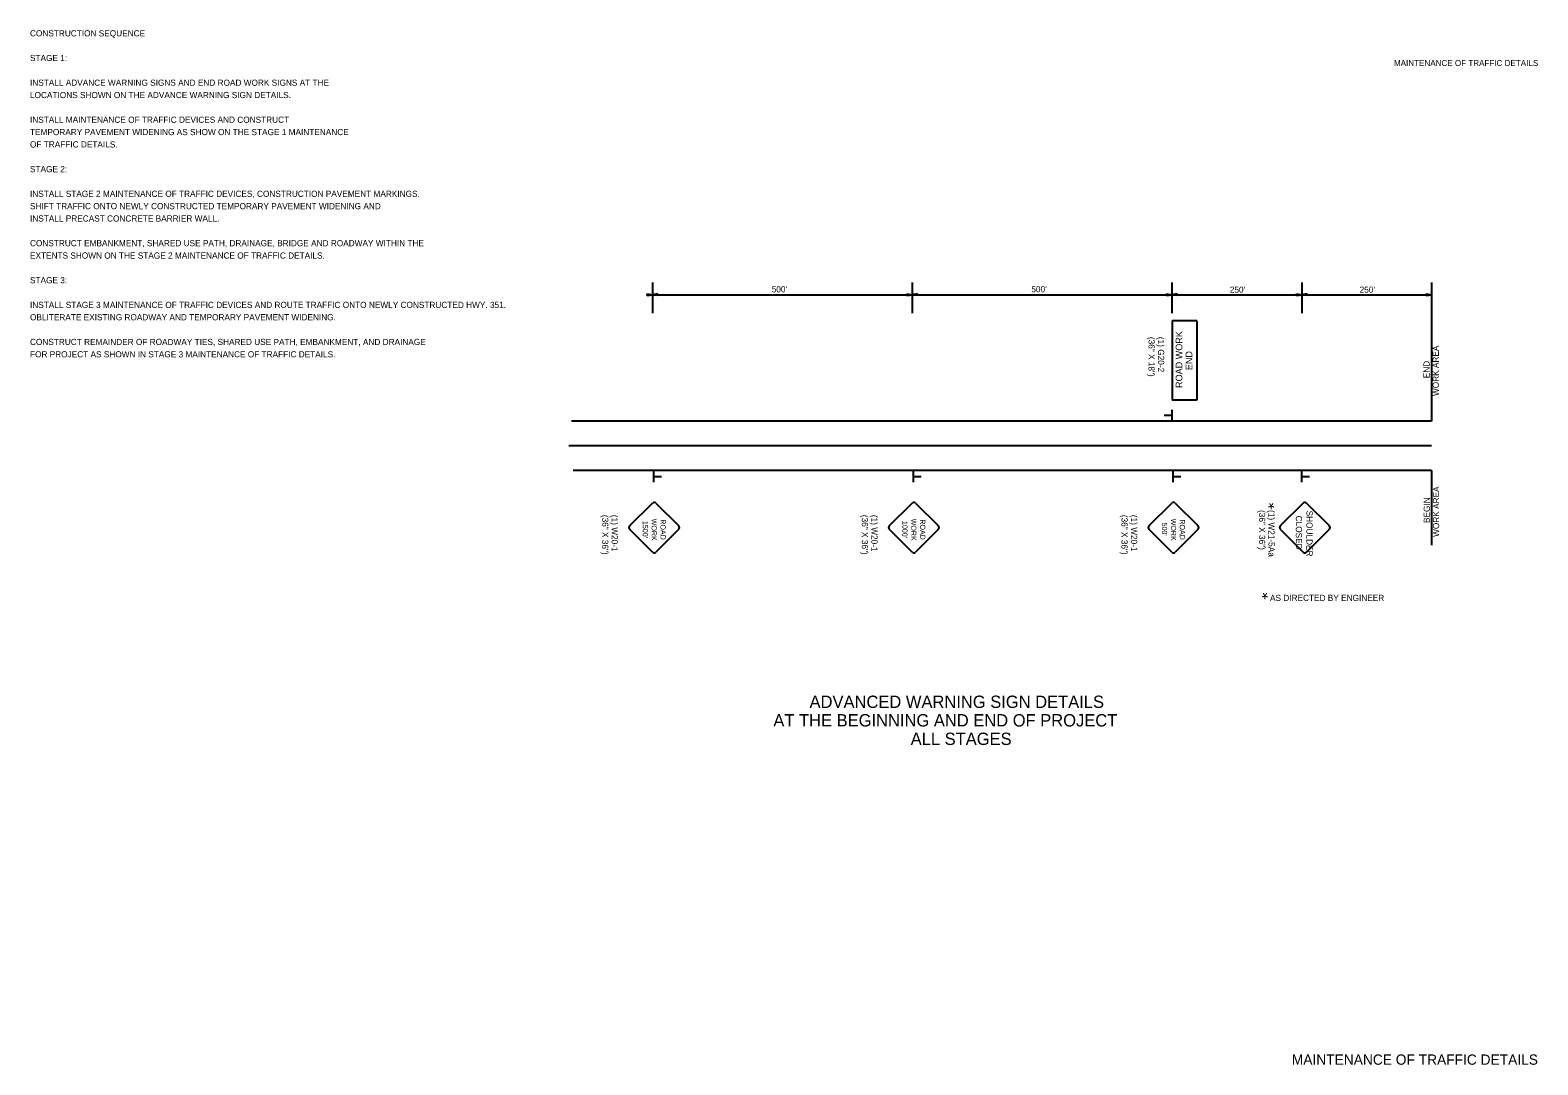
# Model space of a CAD drawing. Extents: x 47 to 1199867, y 39 to 237324.
# Drawn here: x 47 to 1512, y 39 to 1045 of the extents above; entities that cross this region are included whole.
import ezdxf

# ---------------------------------------------------------------- set-up
doc = ezdxf.new("R2010")
doc.units = 0
for name, color, linetype in [('Default', 7, 'Continuous'), ('P_TC_Signs_Permanent', 7, 'Continuous'), ('P_TC_Signs_Temporary', 7, 'Continuous'), ('R_Annotation', 7, 'Continuous'), ('R_Border', 7, 'Continuous'), ('STAMP_Scott', 7, 'Continuous')]:
    doc.layers.add(name, color=color, linetype=linetype)

msp = doc.modelspace()

# ---------------------------------------------------------------- linework, layer by layer
at = {"layer": 'Default'}
for p, q in [((651.8, 799.4), (651.8, 769.6)), ((651.8, 799.4), (651.8, 769.6)), ((904.2, 799.4), (904.2, 769.6)), ((904.2, 799.4), (904.2, 769.6)), ((1156.6, 799.4), (1156.6, 769.6)), ((1282.8, 799.4), (1282.8, 769.6)), ((1409, 799.4), (1409, 664.7)), ((646.6, 788.3), (651.8, 787.5)), ((646.6, 786.7), (646.6, 788.3)), ((646.6, 788.2), (650.9, 787.5)), ((646.6, 788), (650, 787.5)), ((646.6, 787.9), (649.2, 787.5)), ((646.6, 787.8), (648.3, 787.5)), ((646.6, 787.6), (647.4, 787.5)), ((646.6, 786.7), (651.8, 787.5)), ((646.6, 787.3), (648.3, 787.5)), ((646.6, 787), (650, 787.5)), ((646.6, 786.9), (650.9, 787.5)), ((646.6, 787.1), (649.2, 787.5)), ((646.6, 787.4), (647.4, 787.5)), ((657, 788.3), (651.8, 787.5)), ((651.8, 787.5), (778, 787.5)), ((657, 786.7), (651.8, 787.5)), ((657, 788.2), (652.7, 787.5)), ((657, 786.9), (652.7, 787.5)), ((657, 788), (653.6, 787.5)), ((657, 787), (653.6, 787.5)), ((657, 787.9), (654.4, 787.5)), ((657, 787.1), (654.4, 787.5)), ((657, 787.8), (655.3, 787.5)), ((657, 787.3), (655.3, 787.5)), ((657, 787.6), (656.2, 787.5)), ((657, 787.4), (656.2, 787.5)), ((657, 786.7), (657, 788.3)), ((778, 787.5), (904.2, 787.5)), ((899, 788.3), (904.2, 787.5)), ((899, 786.7), (899, 788.3)), ((899, 788.2), (903.3, 787.5)), ((899, 788), (902.4, 787.5)), ((899, 787.9), (901.6, 787.5)), ((899, 787.8), (900.7, 787.5)), ((899, 787.6), (899.8, 787.5)), ((899, 786.7), (904.2, 787.5)), ((899, 787.3), (900.7, 787.5)), ((899, 787), (902.4, 787.5)), ((899, 786.9), (903.3, 787.5)), ((899, 787.1), (901.6, 787.5)), ((899, 787.4), (899.8, 787.5)), ((909.4, 788.3), (904.2, 787.5)), ((904.2, 787.5), (1030.4, 787.5)), ((909.4, 786.7), (904.2, 787.5)), ((909.4, 788.2), (905.1, 787.5)), ((909.4, 786.9), (905.1, 787.5)), ((909.4, 788), (906, 787.5)), ((909.4, 787), (906, 787.5)), ((909.4, 787.9), (906.8, 787.5)), ((909.4, 787.1), (906.8, 787.5)), ((909.4, 787.8), (907.7, 787.5)), ((909.4, 787.3), (907.7, 787.5)), ((909.4, 787.6), (908.6, 787.5)), ((909.4, 787.4), (908.6, 787.5)), ((909.4, 786.7), (909.4, 788.3)), ((1030.4, 787.5), (1156.6, 787.5)), ((1151.4, 788.3), (1156.6, 787.5)), ((1151.4, 786.7), (1151.4, 788.3)), ((1151.4, 788.2), (1155.7, 787.5)), ((1151.4, 788), (1154.9, 787.5)), ((1151.4, 787.9), (1154, 787.5)), ((1151.4, 787.8), (1153.1, 787.5)), ((1151.4, 787.6), (1152.2, 787.5)), ((1151.4, 786.7), (1156.6, 787.5)), ((1151.4, 787.3), (1153.1, 787.5)), ((1151.4, 787), (1154.9, 787.5)), ((1151.4, 786.9), (1155.7, 787.5)), ((1151.4, 787.1), (1154, 787.5)), ((1151.4, 787.4), (1152.2, 787.5)), ((1161.8, 788.3), (1156.6, 787.5)), ((1156.6, 787.5), (1282.8, 787.5)), ((1161.8, 786.7), (1156.6, 787.5)), ((1161.8, 788.2), (1157.5, 787.5)), ((1161.8, 786.9), (1157.5, 787.5)), ((1161.8, 788), (1158.4, 787.5)), ((1161.8, 787), (1158.4, 787.5)), ((1161.8, 787.9), (1159.2, 787.5)), ((1161.8, 787.1), (1159.2, 787.5)), ((1161.8, 787.8), (1160.1, 787.5)), ((1161.8, 787.3), (1160.1, 787.5)), ((1161.8, 787.6), (1161, 787.5)), ((1161.8, 787.4), (1161, 787.5)), ((1161.8, 786.7), (1161.8, 788.3)), ((1277.6, 788.3), (1282.8, 787.5)), ((1277.6, 786.7), (1277.6, 788.3)), ((1277.6, 788.2), (1281.9, 787.5)), ((1277.6, 788), (1281.1, 787.5)), ((1277.6, 787.9), (1280.2, 787.5)), ((1277.6, 787.8), (1279.3, 787.5)), ((1277.6, 787.6), (1278.5, 787.5)), ((1277.6, 786.7), (1282.8, 787.5)), ((1277.6, 787.3), (1279.3, 787.5)), ((1277.6, 787), (1281.1, 787.5)), ((1277.6, 786.9), (1281.9, 787.5)), ((1277.6, 787.1), (1280.2, 787.5)), ((1277.6, 787.4), (1278.5, 787.5)), ((1288, 788.3), (1282.8, 787.5)), ((1282.8, 787.5), (1409, 787.5)), ((1288, 786.7), (1282.8, 787.5)), ((1288, 788.2), (1283.7, 787.5)), ((1288, 786.9), (1283.7, 787.5)), ((1288, 788), (1284.6, 787.5)), ((1288, 787), (1284.6, 787.5)), ((1288, 787.9), (1285.4, 787.5)), ((1288, 787.1), (1285.4, 787.5)), ((1288, 787.8), (1286.3, 787.5)), ((1288, 787.3), (1286.3, 787.5)), ((1288, 787.6), (1287.2, 787.5)), ((1288, 787.4), (1287.2, 787.5)), ((1288, 786.7), (1288, 788.3)), ((1403.8, 788.3), (1409, 787.5)), ((1403.8, 786.7), (1403.8, 788.3)), ((1403.8, 788.2), (1408.1, 787.5)), ((1403.8, 788), (1407.3, 787.5)), ((1403.8, 787.9), (1406.4, 787.5)), ((1403.8, 787.8), (1405.5, 787.5)), ((1403.8, 787.6), (1404.7, 787.5)), ((1403.8, 786.7), (1409, 787.5)), ((1403.8, 787.3), (1405.5, 787.5)), ((1403.8, 787), (1407.3, 787.5)), ((1403.8, 786.9), (1408.1, 787.5)), ((1403.8, 787.1), (1406.4, 787.5)), ((1403.8, 787.4), (1404.7, 787.5)), ((1409, 616.7), (1409, 544))]:
    msp.add_line(p, q, dxfattribs=at)
at = {"layer": 'P_TC_Signs_Permanent'}
for p, q in [((1284.2, 585), (1262, 562.7)), ((1309.7, 562.7), (1287.4, 585)), ((1262, 559.5), (1284.2, 537.2)), ((1287.4, 537.2), (1309.7, 559.5))]:
    msp.add_line(p, q, dxfattribs=at)
for centre, start, end in [((1285.8, 583.4), 45, 135), ((1263.6, 561.1), 135, 225), ((1308.1, 561.1), 315, 45), ((1285.8, 538.8), 225, 315)]:
    msp.add_arc(centre, 2.25, start, end, dxfattribs=at)
at = {"layer": 'P_TC_Signs_Temporary'}
for p, q in [((629.5, 562.7), (651.8, 585)), ((655, 585), (677.2, 562.7)), ((881.9, 562.7), (904.2, 585)), ((907.4, 585), (929.7, 562.7)), ((1134.3, 562.7), (1156.6, 585)), ((1159.8, 585), (1182.1, 562.7)), ((651.8, 537.2), (629.5, 559.5)), ((677.2, 559.5), (655, 537.2)), ((904.2, 537.2), (881.9, 559.5)), ((929.7, 559.5), (907.4, 537.2)), ((1156.6, 537.2), (1134.3, 559.5)), ((1182.1, 559.5), (1159.8, 537.2))]:
    msp.add_line(p, q, dxfattribs=at)
for centre, start, end in [((653.4, 583.4), 45, 135), ((905.8, 583.4), 45, 135), ((1158.2, 583.4), 45, 135), ((631.1, 561.1), 135, 225), ((675.7, 561.1), 315, 45), ((883.5, 561.1), 135, 225), ((928.1, 561.1), 315, 45), ((1135.9, 561.1), 135, 225), ((1180.5, 561.1), 315, 45), ((653.4, 538.8), 225, 315), ((905.8, 538.8), 225, 315), ((1158.2, 538.8), 225, 315)]:
    msp.add_arc(centre, 2.25, start, end, dxfattribs=at)
at = {"layer": 'R_Border'}
for p, q in [((1156.6, 675.5), (1156.6, 664.7)), ((1156.4, 670.1), (1149.1, 670.1)), ((653, 605.3), (653, 616.1)), ((905.4, 605.3), (905.4, 616.1)), ((1157.8, 605.3), (1157.8, 616.1)), ((1282.8, 605.3), (1282.8, 616.1)), ((653.2, 610.7), (660.6, 610.7)), ((905.6, 610.7), (913, 610.7)), ((1158, 610.7), (1165.4, 610.7)), ((1283, 610.7), (1290.3, 610.7))]:
    msp.add_line(p, q, dxfattribs=at)
for points in [[(1409, 664.7), (1240, 664.7), (572.9, 664.7)], [(1409, 640.7), (1240, 640.7), (570.4, 640.7)], [(1409, 616.7), (1240, 616.7), (574.6, 616.7)]]:
    msp.add_lwpolyline(points, dxfattribs=at)
at = {"layer": 'STAMP_Scott'}
for p, q in [((1156.8, 762), (1156.8, 684.9)), ((1181, 762), (1156.8, 762)), ((1181, 762), (1181, 684.9)), ((1181, 684.9), (1156.8, 684.9))]:
    msp.add_line(p, q, dxfattribs=at)

# ---------------------------------------------------------------- texts
at = {"layer": 'Default'}
for s, p in [("500'", (767.6, 789.8)), ("500'", (1020, 789.8)), ("250'", (1212.9, 789.4)), ("250'", (1339.1, 789.4))]:
    msp.add_text(s, height=6, rotation=360, dxfattribs=at).set_placement(p)
at = {"layer": 'P_TC_Signs_Permanent'}
for s, p in [('CLOSED', (1277.1, 572.7)), ('SHOULDER', (1287.4, 577.6))]:
    msp.add_text(s, height=6, rotation=270, dxfattribs=at).set_placement(p)
at = {"layer": 'P_TC_Signs_Temporary'}
for s, p in [("1500'", (642.2, 567.6)), ('WORK', (650.8, 569.8)), (' ROAD ', (659.5, 571.1)), ("1000'", (894.6, 567.6)), ('WORK', (903.2, 569.8)), (' ROAD ', (911.9, 571.1)), ("500'", (1147, 566)), ('WORK', (1155.7, 569.8)), (' ROAD ', (1164.3, 571.1))]:
    msp.add_text(s, height=5, rotation=270, dxfattribs=at).set_placement(p)
at = {"layer": 'R_Annotation'}
for s, p in [('CONSTRUCTION SEQUENCE', (46.6, 1038.6)), ('STAGE 1:', (46.6, 1014.6)), ('INSTALL ADVANCE WARNING SIGNS AND END ROAD WORK SIGNS AT THE', (46.6, 990.6)), ('LOCATIONS SHOWN ON THE ADVANCE WARNING SIGN DETAILS.  ', (46.6, 978.6)), ('INSTALL MAINTENANCE OF TRAFFIC DEVICES AND CONSTRUCT ', (46.6, 954.6)), ('TEMPORARY PAVEMENT WIDENING AS SHOW ON THE STAGE 1 MAINTENANCE ', (46.6, 942.6)), ('OF TRAFFIC DETAILS. ', (46.6, 930.6)), ('STAGE 2:', (46.6, 906.6)), ('INSTALL STAGE 2 MAINTENANCE OF TRAFFIC DEVICES, CONSTRUCTION PAVEMENT MARKINGS. ', (46.6, 882.6)), ('SHIFT TRAFFIC ONTO NEWLY CONSTRUCTED TEMPORARY PAVEMENT WIDENING AND ', (46.6, 870.6)), ('INSTALL PRECAST CONCRETE BARRIER WALL. ', (46.6, 858.6)), ('CONSTRUCT EMBANKMENT, SHARED USE PATH, DRAINAGE, BRIDGE AND ROADWAY WITHIN THE', (46.6, 834.6)), ('EXTENTS SHOWN ON THE STAGE 2 MAINTENANCE OF TRAFFIC DETAILS.', (46.6, 822.6)), ('STAGE 3:', (46.6, 798.6)), ('INSTALL STAGE 3 MAINTENANCE OF TRAFFIC DEVICES AND ROUTE TRAFFIC ONTO NEWLY CONSTRUCTED HWY. 351. ', (46.6, 774.6)), ('OBLITERATE EXISTING ROADWAY AND TEMPORARY PAVEMENT WIDENING. ', (46.6, 762.6)), ('CONSTRUCT REMAINDER OF ROADWAY TIES, SHARED USE PATH, EMBANKMENT, AND DRAINAGE', (46.6, 738.6)), ('FOR PROJECT AS SHOWN IN STAGE 3 MAINTENANCE OF TRAFFIC DETAILS.', (46.6, 726.6)), ('AS DIRECTED BY ENGINEER', (1252, 489.8))]:
    msp.add_text(s, height=6, dxfattribs=at).set_placement(p)
for s, height, rotation, p in [('ROAD WORK', 6.59, 90, (1166.8, 696.8)), ('(36" X 18")', 6, 270, (1133.9, 746.5)), ('(1) G20-2', 6, 270, (1143.1, 746.5)), ('WORK AREA', 6, 90, (1416.1, 689)), ('END', 6.59, 90, (1176.5, 714.1)), ('END', 6, 90, (1407.1, 706.3)), ('WORK AREA', 6, 90, (1416.4, 552.1)), ('BEGIN', 6, 90, (1407.4, 565.6)), ('(36" X 36")', 6, 270, (602.8, 573.5)), ('(1) W20-1', 6, 270, (612, 573.5)), ('(36" X 36")', 6, 270, (855.2, 573.5)), ('(1) W20-1', 6, 270, (864.5, 573.5)), ('(36" X 36")', 6, 270, (1107.6, 573.5)), ('(1) W20-1', 6, 270, (1116.9, 573.5)), ('(36" X 36")', 6, 270, (1241.3, 578.2)), ('(1) W21-5Aa', 6, 270, (1250.5, 578.2)), ('*', 12, 180, (1256.3, 590.9)), ('*', 12, 180, (1250.2, 503.5)), ('ADVANCED WARNING SIGN DETAILS', 12, 360, (804.4, 385.8)), ('AT THE BEGINNING AND END OF PROJECT', 12, 360, (769.2, 367.8)), ('ALL STAGES', 12, 360, (902.7, 349.8)), ('MAINTENANCE OF TRAFFIC DETAILS', 10, 360, (1273.2, 39))]:
    msp.add_text(s, height=height, rotation=rotation, dxfattribs=at).set_placement(p)
at = {"layer": 'R_Border'}
msp.add_text('MAINTENANCE OF TRAFFIC DETAILS', height=5.862, rotation=360, dxfattribs=at).set_placement((1372.5, 1009.8))

doc.saveas('drawing.dxf')
